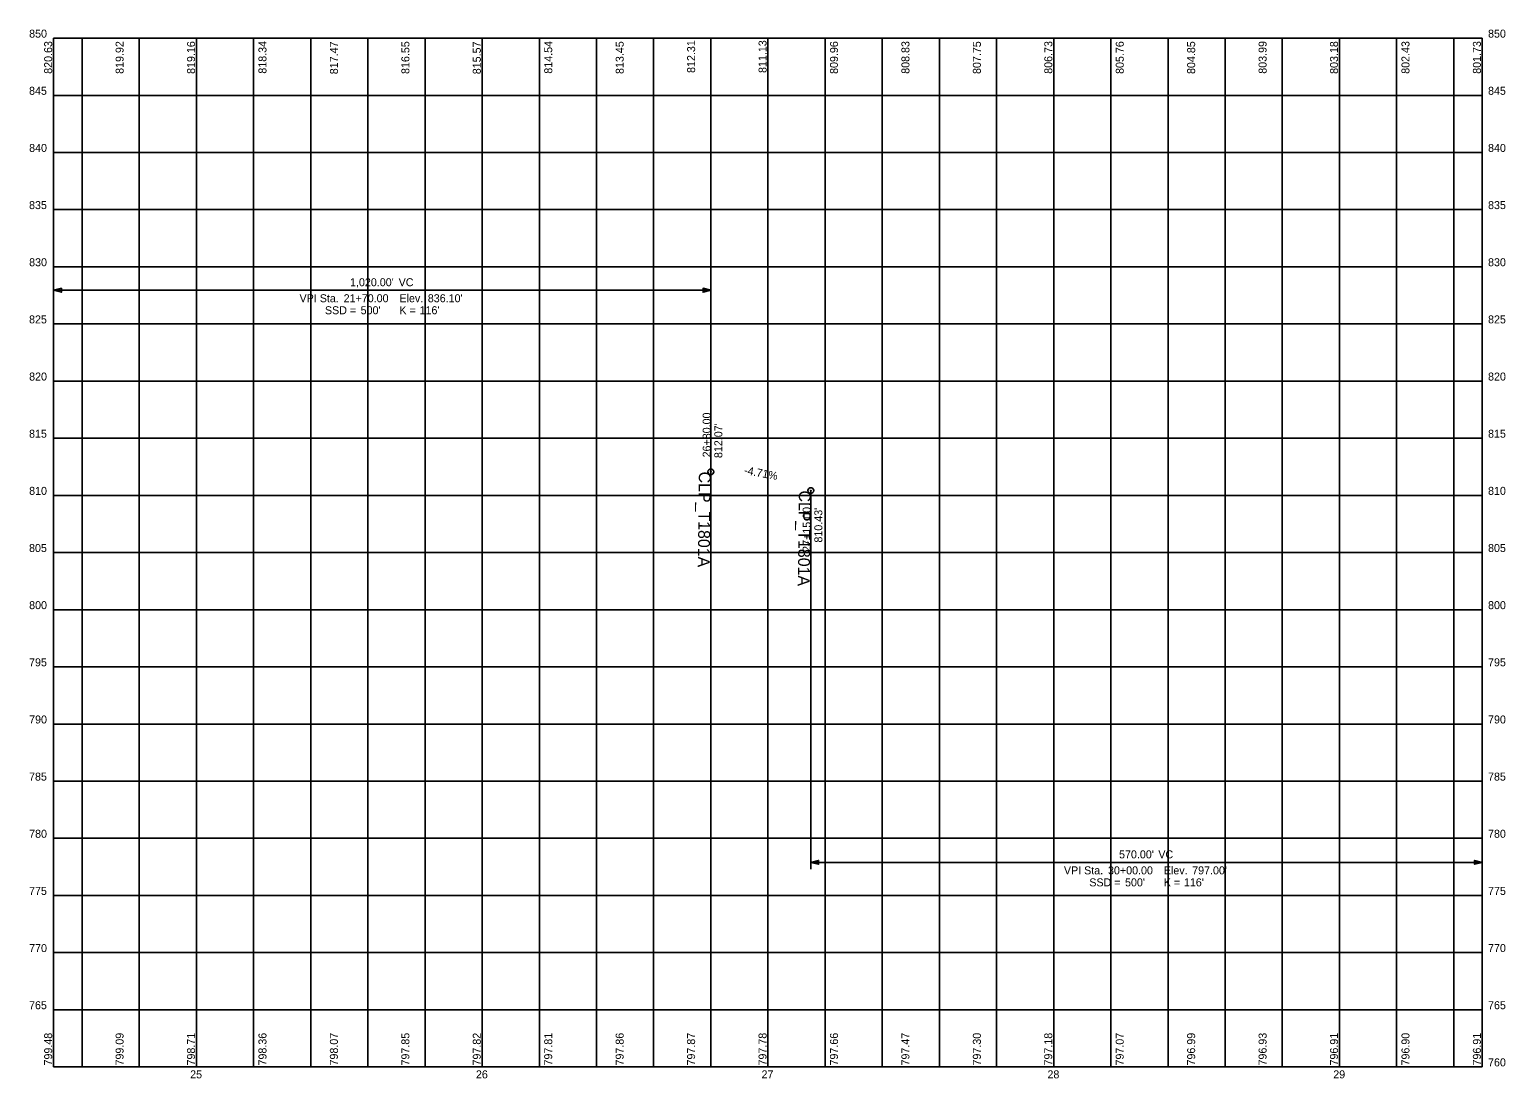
# Model space of a CAD drawing. Extents: x 1672 to 2189, y 756 to 1123.
import ezdxf

# ---------------------------------------------------------------- set-up
doc = ezdxf.new("R2010")
doc.units = 0
for name, color, linetype in [('Default', 7, 'Continuous'), ('PF_P_Text', 7, 'Continuous'), ('PF_P_Text_Strip_Grades_20', 7, 'Continuous'), ('SH_Major_Grid_Line', 7, 'Continuous')]:
    doc.layers.add(name, color=color, linetype=linetype)

msp = doc.modelspace()

# ---------------------------------------------------------------- linework, layer by layer
at = {"layer": 'Default'}
for centre in [(1910.78, 968.3), (1945.78, 961.7)]:
    msp.add_circle(centre, 0.1, dxfattribs=at)
at = {"layer": 'PF_P_Text'}
for p, q in [((1910.78, 1013.04), (1910.78, 1034.07)), ((1680.78, 1031.9), (1680.78, 1031.7)), ((1680.78, 1031.8), (1910.78, 1031.8)), ((1910.78, 1031.7), (1910.78, 1031.9)), ((1910.78, 968.3), (1910.78, 1013.04)), ((1945.78, 961.7), (1945.78, 878.2)), ((1945.78, 878.2), (1945.78, 829.21)), ((1945.78, 831.69), (1945.78, 831.49)), ((2180.78, 831.49), (2180.78, 831.69)), ((1945.78, 831.59), (2180.78, 831.59))]:
    msp.add_line(p, q, dxfattribs=at)
for points in [[(1680.78, 1031.8), (1683.5, 1032.48), (1683.5, 1031.12)], [(1910.78, 1031.8), (1908.06, 1031.12), (1908.06, 1032.48)], [(1945.78, 831.59), (1948.5, 832.27), (1948.5, 830.91)], [(2180.78, 831.59), (2178.06, 830.91), (2178.06, 832.27)]]:
    msp.add_lwpolyline(points, close=True, dxfattribs=at)
for centre in [(1910.78, 968.3), (1945.78, 961.7)]:
    msp.add_circle(centre, 1, dxfattribs=at)
at = {"layer": 'SH_Major_Grid_Line'}
for p, q in [((1680.78, 1120), (2180.78, 1120)), ((1680.78, 760), (1680.78, 1120)), ((1690.78, 760), (1690.78, 1120)), ((1710.78, 760), (1710.78, 1120)), ((1730.78, 760), (1730.78, 1120)), ((1750.78, 760), (1750.78, 1120)), ((1770.78, 760), (1770.78, 1120)), ((1790.78, 760), (1790.78, 1120)), ((1810.78, 760), (1810.78, 1120)), ((1830.78, 760), (1830.78, 1120)), ((1850.78, 760), (1850.78, 1120)), ((1870.78, 760), (1870.78, 1120)), ((1890.78, 760), (1890.78, 1120)), ((1910.78, 760), (1910.78, 1120)), ((1930.78, 760), (1930.78, 1120)), ((1950.78, 760), (1950.78, 1120)), ((1970.78, 760), (1970.78, 1120)), ((1990.78, 760), (1990.78, 1120)), ((2010.78, 760), (2010.78, 1120)), ((2030.78, 760), (2030.78, 1120)), ((2050.78, 760), (2050.78, 1120)), ((2070.78, 760), (2070.78, 1120)), ((2090.78, 760), (2090.78, 1120)), ((2110.78, 760), (2110.78, 1120)), ((2130.78, 760), (2130.78, 1120)), ((2150.78, 760), (2150.78, 1120)), ((2170.78, 760), (2170.78, 1120)), ((2180.78, 760), (2180.78, 1120)), ((1680.78, 1100), (2180.78, 1100)), ((1680.78, 1080), (2180.78, 1080)), ((1680.78, 1060), (2180.78, 1060)), ((1680.78, 1040), (2180.78, 1040)), ((1680.78, 1020), (2180.78, 1020)), ((1680.78, 1000), (2180.78, 1000)), ((1680.78, 980), (2180.78, 980)), ((1680.78, 960), (2180.78, 960)), ((1680.78, 940), (2180.78, 940)), ((1680.78, 920), (2180.78, 920)), ((1680.78, 900), (2180.78, 900)), ((1680.78, 880), (2180.78, 880)), ((1680.78, 860), (2180.78, 860)), ((1680.78, 840), (2180.78, 840)), ((1680.78, 820), (2180.78, 820)), ((1680.78, 800), (2180.78, 800)), ((1680.78, 780), (2180.78, 780)), ((1680.78, 760), (2180.78, 760))]:
    msp.add_line(p, q, dxfattribs=at)

# ---------------------------------------------------------------- texts
at = {"layer": 'Default'}
for s, height, rotation, p in [('CLP_T1801A', 4.167, 269.3253, (1906.61, 968.35)), ('-4.71%', 2.8, 349.3287, (1922.26, 967.54)), ('CLP_T1801A', 4.167, 269.3253, (1941.61, 961.75))]:
    msp.add_text(s, height=height, rotation=rotation, dxfattribs=at).set_placement(p)
at = {"layer": 'PF_P_Text'}
for s, p in [('850', (1672.22, 1120.2)), ('850', (2182.78, 1120.2)), ('845', (1672.19, 1100.2)), ('845', (2182.78, 1100.2)), ('840', (1672.22, 1080.2)), ('840', (2182.78, 1080.2)), ('835', (1672.19, 1060.2)), ('835', (2182.78, 1060.2)), ('830', (1672.22, 1040.2)), ('830', (2182.78, 1040.2)), ("1,020.00'", (1784.52, 1033.2)), (' VC', (1800.49, 1033.2)), ('VPI Sta. ', (1766.85, 1027.6)), ('21+70.00', (1782.28, 1027.6)), ('   Elev. ', (1798.7, 1027.6)), ("836.10'", (1811.74, 1027.6)), ('825', (1672.19, 1020.2)), ('SSD = ', (1775.74, 1023.4)), ("500'", (1788.24, 1023.4)), ('K = ', (1801.78, 1023.4)), ("116'", (1808.85, 1023.4)), ('825', (2182.78, 1020.2)), ('820', (1672.22, 1000.2)), ('820', (2182.78, 1000.2)), ('815', (1672.19, 980.2)), ('815', (2182.78, 980.2)), ('810', (1672.22, 960.2)), ('810', (2182.78, 960.2)), ('805', (1672.19, 940.2)), ('805', (2182.78, 940.2)), ('800', (1672.22, 920.2)), ('800', (2182.78, 920.2)), ('795', (1672.19, 900.2)), ('795', (2182.78, 900.2)), ('790', (1672.22, 880.2)), ('790', (2182.78, 880.2)), ('785', (1672.19, 860.2)), ('785', (2182.78, 860.2)), ('780', (1672.22, 840.2)), ('780', (2182.78, 840.2)), ("570.00'", (2053.65, 832.99)), (' VC', (2066.36, 832.99)), ('VPI Sta. ', (2034.35, 827.39)), ('30+00.00', (2049.78, 827.39)), ('   Elev. ', (2066.2, 827.39)), ("797.00'", (2079.24, 827.39)), ('775', (1672.19, 820.2)), ('SSD = ', (2043.24, 823.19)), ("500'", (2055.74, 823.19)), ('K = ', (2069.28, 823.19)), ("116'", (2076.35, 823.19)), ('775', (2182.78, 820.2)), ('770', (1672.22, 800.2)), ('770', (2182.78, 800.2)), ('765', (1672.19, 780.2)), ('765', (2182.78, 780.2)), ('760', (2182.78, 760.2)), ('25', (1728.57, 756)), ('26', (1828.58, 756)), ('27', (1928.53, 756)), ('28', (2028.59, 756)), ('29', (2128.61, 756))]:
    msp.add_text(s, height=2.8, dxfattribs=at).set_placement(p)
for s, p in [('26+80.00', (1910.73, 973.3)), ("812.07'", (1914.81, 973.07)), ('27+15.00', (1945.73, 940.25)), ("810.43'", (1949.81, 943.5)), ('799.48', (1680.28, 760.5)), ('799.09', (1705.28, 760.5)), ('798.71', (1730.28, 760.5)), ('798.36', (1755.28, 760.5)), ('798.07', (1780.28, 760.5)), ('797.85', (1805.28, 760.5)), ('797.82', (1830.28, 760.5)), ('797.81', (1855.28, 760.5)), ('797.86', (1880.28, 760.5)), ('797.87', (1905.28, 760.5)), ('797.78', (1930.28, 760.5)), ('797.66', (1955.28, 760.5)), ('797.47', (1980.28, 760.5)), ('797.30', (2005.28, 760.5)), ('797.18', (2030.28, 760.5)), ('797.07', (2055.28, 760.5)), ('796.99', (2080.28, 760.5)), ('796.93', (2105.28, 760.5)), ('796.91', (2130.28, 760.5)), ('796.90', (2155.28, 760.5)), ('796.91', (2180.28, 760.5))]:
    msp.add_text(s, height=2.8, rotation=90, dxfattribs=at).set_placement(p)
at = {"layer": 'PF_P_Text_Strip_Grades_20'}
for s, p in [('820.63', (1680.28, 1107.54)), ('819.92', (1705.28, 1107.52)), ('819.16', (1730.28, 1107.5)), ('818.34', (1755.28, 1107.59)), ('817.47', (1780.29, 1107.39)), ('816.55', (1805.29, 1107.48)), ('815.57', (1830.29, 1107.39)), ('814.54', (1855.29, 1107.59)), ('813.45', (1880.29, 1107.48)), ('812.31', (1905.29, 1107.84)), ('811.13', (1930.29, 1107.83)), ('809.96', (1955.29, 1107.5)), ('808.83', (1980.29, 1107.54)), ('807.75', (2005.29, 1107.48)), ('806.73', (2030.29, 1107.54)), ('805.76', (2055.29, 1107.5)), ('804.85', (2080.28, 1107.48)), ('803.99', (2105.28, 1107.56)), ('803.18', (2130.28, 1107.51)), ('802.43', (2155.28, 1107.54)), ('801.73', (2180.28, 1107.54))]:
    msp.add_text(s, height=2.8, rotation=90, dxfattribs=at).set_placement(p)

doc.saveas('drawing.dxf')
